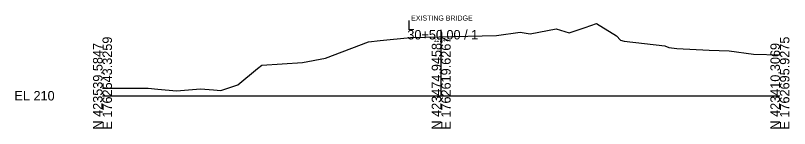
# Model space of a CAD drawing. Extents: x -26 to 3203, y -11010 to 4024.
# Drawn here: x 974.3 to 1202.8, y -5009.7 to -4976.3 of the extents above; entities that cross this region are included whole.
import ezdxf

# ---------------------------------------------------------------- set-up
doc = ezdxf.new("R2010")
doc.units = 0
for name, color, linetype in [('Default', 7, 'Continuous'), ('Exist Cross Section Cell', 7, 'Continuous'), ('Exist XS Center Line Elevation Label', 7, 'Continuous'), ('Exist XS Ground Line', 7, 'Continuous'), ('Prop XS SE Text', 7, 'Continuous')]:
    doc.layers.add(name, color=color, linetype=linetype)

msp = doc.modelspace()

# ---------------------------------------------------------------- linework, layer by layer
at = {"layer": 'Exist Cross Section Cell'}
for p, q in [((1100, -5000), (1100, -4980.55)), ((1000, -5000), (1100, -5000)), ((1100, -5000), (1200, -5000))]:
    msp.add_line(p, q, dxfattribs=at)
at = {"layer": 'Exist XS Ground Line'}
msp.add_lwpolyline([(1000, -4997.72), (1013.49, -4997.8), (1016.35, -4998.03), (1021.85, -4998.52), (1028.97, -4997.97), (1032.82, -4998.21), (1034.96, -4998.46), (1039.92, -4996.81), (1045.77, -4991.92), (1047.01, -4990.92), (1059.07, -4990.13), (1065.81, -4988.93), (1078.51, -4984.06), (1081.99, -4983.7), (1090.96, -4982.74), (1116.3, -4982.23), (1123.32, -4981.19), (1126.27, -4981.67), (1133.95, -4980.22), (1137.8, -4981.4), (1142.53, -4979.79), (1145.9, -4978.64), (1151.79, -4982.24), (1152.91, -4983.59), (1154.06, -4983.89), (1166.02, -4985.29), (1167.2, -4985.78), (1169.53, -4985.99), (1179.13, -4986.57), (1185, -4986.75), (1192.23, -4987.69), (1200, -4987.89)], dxfattribs=at)
msp.add_lwpolyline([(1000, -4997.72), (1013.49, -4997.8), (1016.35, -4998.03), (1021.85, -4998.52), (1028.97, -4997.97), (1032.82, -4998.21), (1034.96, -4998.46), (1039.92, -4996.81), (1045.77, -4991.92), (1047.01, -4990.92), (1059.07, -4990.13), (1065.81, -4988.93), (1078.51, -4984.06), (1081.99, -4983.7), (1090.96, -4982.74), (1116.3, -4982.23), (1123.32, -4981.19), (1126.27, -4981.67), (1133.95, -4980.22), (1137.8, -4981.4), (1142.53, -4979.79), (1145.9, -4978.64), (1151.79, -4982.24), (1152.91, -4983.59), (1154.06, -4983.89), (1166.02, -4985.29), (1167.2, -4985.78), (1169.53, -4985.99), (1179.13, -4986.57), (1185, -4986.75), (1192.23, -4987.69), (1200, -4987.89)], dxfattribs=at)
msp.add_lwpolyline([(1000, -4997.72), (1013.49, -4997.8), (1016.35, -4998.03), (1021.85, -4998.52), (1028.97, -4997.97), (1032.82, -4998.21), (1034.96, -4998.46), (1039.92, -4996.81), (1045.77, -4991.92), (1047.01, -4990.92), (1059.07, -4990.13), (1065.81, -4988.93), (1078.51, -4984.06), (1081.99, -4983.7), (1090.96, -4982.74), (1116.3, -4982.23), (1123.32, -4981.19), (1126.27, -4981.67), (1133.95, -4980.22), (1137.8, -4981.4), (1142.53, -4979.79), (1145.9, -4978.64), (1151.79, -4982.24), (1152.91, -4983.59), (1154.06, -4983.89), (1166.02, -4985.29), (1167.2, -4985.78), (1169.53, -4985.99), (1179.13, -4986.57), (1185, -4986.75), (1192.23, -4987.69), (1200, -4987.89)], dxfattribs=at)
msp.add_lwpolyline([(1000, -4997.72), (1013.49, -4997.8), (1016.35, -4998.03), (1021.85, -4998.52), (1028.97, -4997.97), (1032.82, -4998.21), (1034.96, -4998.46), (1039.92, -4996.81), (1045.77, -4991.92), (1047.01, -4990.92), (1059.07, -4990.13), (1065.81, -4988.93), (1078.51, -4984.06), (1081.99, -4983.7), (1090.96, -4982.74), (1116.3, -4982.23), (1123.32, -4981.19), (1126.27, -4981.67), (1133.95, -4980.22), (1137.8, -4981.4), (1142.53, -4979.79), (1145.9, -4978.64), (1151.79, -4982.24), (1152.91, -4983.59), (1154.06, -4983.89), (1166.02, -4985.29), (1167.2, -4985.78), (1169.53, -4985.99), (1179.13, -4986.57), (1185, -4986.75), (1192.23, -4987.69), (1200, -4987.89)], dxfattribs=at)
msp.add_lwpolyline([(1000, -4997.72), (1013.49, -4997.8), (1016.35, -4998.03), (1021.85, -4998.52), (1028.97, -4997.97), (1032.82, -4998.21), (1034.96, -4998.46), (1039.92, -4996.81), (1045.77, -4991.92), (1047.01, -4990.92), (1059.07, -4990.13), (1065.81, -4988.93), (1078.51, -4984.06), (1081.99, -4983.7), (1090.96, -4982.74), (1116.3, -4982.23), (1123.32, -4981.19), (1126.27, -4981.67), (1133.95, -4980.22), (1137.8, -4981.4), (1142.53, -4979.79), (1145.9, -4978.64), (1151.79, -4982.24), (1152.91, -4983.59), (1154.06, -4983.89), (1166.02, -4985.29), (1167.2, -4985.78), (1169.53, -4985.99), (1179.13, -4986.57), (1185, -4986.75), (1192.23, -4987.69), (1200, -4987.89)], dxfattribs=at)

# ---------------------------------------------------------------- texts
at = {"layer": 'Default'}
msp.add_text('-', height=0.0001, dxfattribs=at).set_placement((1000, -5000))
at = {"layer": 'Exist Cross Section Cell'}
for s, p in [('L', (1090, -4980.55)), ('30+50.00 / 1', (1090, -4983.35)), ('EL 210', (974, -5001.4))]:
    msp.add_text(s, height=2.8, dxfattribs=at).set_placement(p)
for s, p in [('E 1762543.3259', (1002.8, -5010)), ('E 1762619.6267', (1102.8, -5010)), ('E 1762695.9275', (1202.8, -5010)), ('N 423539.5847', (1000, -5010)), ('N 423474.9458', (1100, -5010)), ('N 423410.3069', (1200, -5010))]:
    msp.add_text(s, height=2.8, rotation=90, dxfattribs=at).set_placement(p)
at = {"layer": 'Exist XS Center Line Elevation Label'}
msp.add_text('227.44', height=1, dxfattribs=at).set_placement((1097.86, -4984.06))
at = {"layer": 'Prop XS SE Text'}
msp.add_text('EXISTING BRIDGE', height=1.5, rotation=360, dxfattribs=at).set_placement((1091.12, -4977.78))

doc.saveas('drawing.dxf')
